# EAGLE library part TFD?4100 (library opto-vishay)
2.7 V to 5.5 V Serial Infrared Transceiver Module Family (SIR, 115.2 kbit/s) Vishay Telefunken
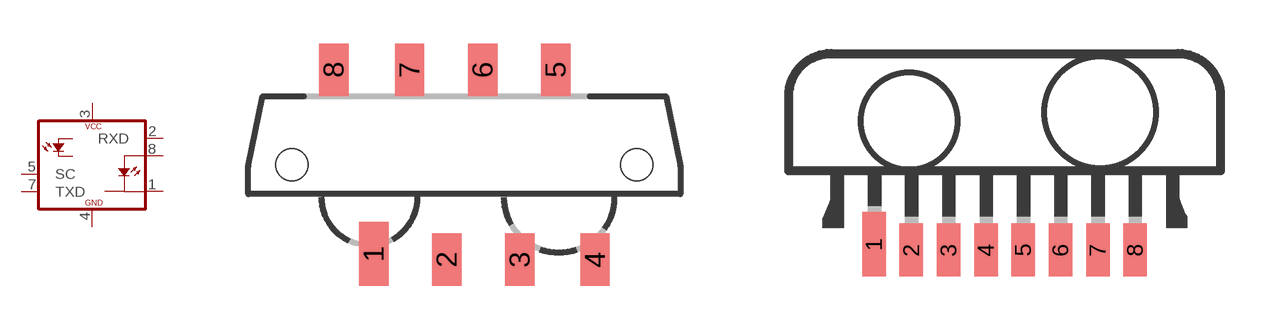
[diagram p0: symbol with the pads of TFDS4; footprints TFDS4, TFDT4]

Designator prefix -

## TFDS4100  [TFDS4]
1  IRED-C  out
2  RXD  out
3  VCC  pwr
4  GND  pwr
5  SC  in
7  TXD  in
8  IRED-A  pas

## TFDT4100  [TFDT4]
1  IRED-A  pas
2  IRED-C  out
3  TXD  in
4  RXD  out
6  VCC  pwr
7  SC  in
8  GND  pwr

## TFDUH4100  [TFDU4-HOR]
Pads as for TFDT4

## TFDUV4100  [TFDU4-VER]
Pads as for TFDT4

## Footprint TFDS4 (pad centres in mm)
TFDS4500 Side View Package Vishay Telefunken
smd 1 x 2.2: 1 -3.1,-3.05
smd 1 x 1.8: 2 -0.6,-3.25; 3 1.9,-3.25; 4 4.48,-3.25; 5 3.13,3.25; 6 0.63,3.25; 7 -1.87,3.25; 8 -4.47,3.25
hole 1.1 at -5.9,0
hole 1.1 at 5.9,0

## Footprint TFDT4 (pad centres in mm)
TFDS4100 Top View Vishay Telefunken
smd 0.8 x 2.2: 1 -4.445,0.2
smd 0.8 x 1.8: 2 -3.175,0; 3 -1.905,0; 4 -0.635,0; 5 0.635,0; 6 1.905,0; 7 3.175,0; 8 4.445,0

## Footprint TFDU4-HOR (pad centres in mm)
TFDU4100 BabyFace horizontal (Universal) Vishay Telefunken
smd 0.6 x 2.5: 1 -3.5,0; 2 -2.5,0; 3 -1.5,0; 4 -0.5,0; 5 0.5,0; 6 1.5,0; 7 2.5,0; 8 3.5,0

## Footprint TFDU4-VER (pad centres in mm)
TFDU4100 BabyFace vertical (Universal) Vishay Telefunken
smd 0.6 x 2.5: 1 -3.5,-0.9; 2 -2.5,-0.9; 3 -1.5,-0.9; 4 -0.5,-0.9; 5 0.5,-0.9; 6 1.5,-0.9; 7 2.5,-0.9; 8 3.5,-0.9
